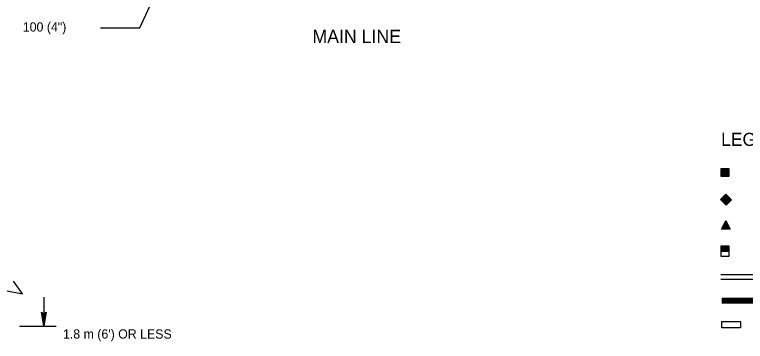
# Model space of a CAD drawing. Extents: x 639362 to 641108, y 298458 to 299646.
# Drawn here: x 639841.8 to 640079.2, y 299345.9 to 299452 of the extents above; entities that cross this region are included whole.
import ezdxf

# ---------------------------------------------------------------- set-up
doc = ezdxf.new("R2010")
doc.units = 0
doc.layers.add('2', color=7, linetype='Continuous')

msp = doc.modelspace()

# ---------------------------------------------------------------- linework, layer by layer
at = {"layer": '2'}
for p, q in [((639882.43, 299447.68), (639888.96, 299461.75)), ((639869.74, 299447.68), (639882.43, 299447.68)), ((640071.33, 299402.08), (640073.83, 299402.08)), ((640071.33, 299399.43), (640071.33, 299402.08)), ((640071.51, 299401.95), (640073.64, 299401.95)), ((640071.51, 299399.55), (640071.51, 299401.95)), ((640071.69, 299401.77), (640073.47, 299401.77)), ((640071.69, 299399.73), (640071.69, 299401.77)), ((640071.87, 299401.59), (640073.29, 299401.59)), ((640071.87, 299399.91), (640071.87, 299401.59)), ((640072.05, 299401.41), (640073.11, 299401.41)), ((640072.05, 299400.08), (640072.05, 299401.41)), ((640072.22, 299400.26), (640072.22, 299401.24)), ((640072.22, 299401.24), (640072.93, 299401.24)), ((640072.93, 299401.24), (640072.93, 299400.26)), ((640073.11, 299401.41), (640073.11, 299400.08)), ((640073.29, 299401.59), (640073.29, 299399.91)), ((640073.47, 299401.77), (640073.47, 299399.73)), ((640073.64, 299401.95), (640073.64, 299399.55)), ((640073.83, 299402.08), (640073.83, 299399.43)), ((640073.83, 299399.43), (640071.33, 299399.43)), ((640073.64, 299399.55), (640071.51, 299399.55)), ((640073.47, 299399.73), (640071.69, 299399.73)), ((640073.29, 299399.91), (640071.87, 299399.91)), ((640073.11, 299400.08), (640072.05, 299400.08)), ((640072.93, 299400.26), (640072.22, 299400.26)), ((640072.4, 299401.06), (640072.76, 299401.06)), ((640072.4, 299400.44), (640072.4, 299401.06)), ((640072.76, 299400.44), (640072.4, 299400.44)), ((640072.58, 299400.88), (640072.58, 299400.62)), ((640072.76, 299401.06), (640072.76, 299400.44)), ((640071.05, 299392.01), (640072.81, 299393.78)), ((640072.92, 299390.14), (640071.05, 299392.01)), ((640071.27, 299392.05), (640072.78, 299393.55)), ((640072.96, 299390.36), (640071.27, 299392.05)), ((640071.52, 299392.05), (640072.78, 299393.31)), ((640072.96, 299390.61), (640071.52, 299392.05)), ((640071.77, 299392.05), (640072.78, 299393.05)), ((640072.96, 299390.86), (640071.77, 299392.05)), ((640072.02, 299392.05), (640072.78, 299392.8)), ((640072.96, 299391.11), (640072.02, 299392.05)), ((640072.28, 299392.05), (640072.78, 299392.55)), ((640072.96, 299391.36), (640072.28, 299392.05)), ((640072.53, 299392.05), (640072.78, 299392.3)), ((640072.97, 299391.61), (640072.53, 299392.05)), ((640072.77, 299392.05), (640072.96, 299391.86)), ((640072.78, 299393.55), (640074.47, 299391.86)), ((640072.78, 299393.31), (640074.22, 299391.86)), ((640072.78, 299393.05), (640073.97, 299391.86)), ((640072.78, 299392.8), (640073.72, 299391.86)), ((640072.78, 299392.55), (640073.47, 299391.86)), ((640072.78, 299392.3), (640073.22, 299391.86)), ((640072.81, 299393.78), (640074.69, 299391.9)), ((640074.69, 299391.9), (640072.92, 299390.14)), ((640074.47, 299391.86), (640072.96, 299390.36)), ((640074.22, 299391.86), (640072.96, 299390.61)), ((640073.97, 299391.86), (640072.96, 299390.86)), ((640073.72, 299391.86), (640072.96, 299391.11)), ((640073.47, 299391.86), (640072.96, 299391.36)), ((640073.22, 299391.86), (640072.97, 299391.61)), ((640071.4, 299382.38), (640072.78, 299385.15)), ((640071.56, 299382.48), (640072.79, 299384.93)), ((640071.72, 299382.58), (640072.78, 299384.71)), ((640072.78, 299385.15), (640074.17, 299382.38)), ((640072.78, 299384.71), (640073.85, 299382.58)), ((640072.79, 299384.93), (640074.01, 299382.48)), ((640074.17, 299382.38), (640071.4, 299382.38)), ((640074.01, 299382.48), (640071.56, 299382.48)), ((640073.85, 299382.58), (640071.72, 299382.58)), ((640071.88, 299382.67), (640072.79, 299384.49)), ((640073.69, 299382.68), (640071.88, 299382.67)), ((640072.04, 299382.78), (640072.79, 299384.27)), ((640073.53, 299382.77), (640072.04, 299382.78)), ((640072.2, 299382.87), (640072.78, 299384.05)), ((640073.37, 299382.87), (640072.2, 299382.87)), ((640072.36, 299382.97), (640072.79, 299383.83)), ((640073.21, 299382.97), (640072.36, 299382.97)), ((640072.52, 299383.08), (640072.78, 299383.6)), ((640073.05, 299383.07), (640072.52, 299383.08)), ((640072.67, 299383.17), (640072.78, 299383.38)), ((640072.89, 299383.17), (640072.67, 299383.17)), ((640072.78, 299384.05), (640073.37, 299382.87)), ((640072.78, 299383.6), (640073.05, 299383.07)), ((640072.78, 299383.38), (640072.89, 299383.17)), ((640072.79, 299384.49), (640073.69, 299382.68)), ((640072.79, 299384.27), (640073.53, 299382.77)), ((640072.79, 299383.83), (640073.21, 299382.97)), ((640071.27, 299376.9), (640073.77, 299376.9)), ((640071.27, 299375.21), (640071.27, 299376.9)), ((640073.77, 299375.21), (640071.27, 299375.21)), ((640071.45, 299376.82), (640073.58, 299376.82)), ((640071.45, 299375.29), (640071.45, 299376.82)), ((640073.58, 299375.29), (640071.45, 299375.29)), ((640071.63, 299376.71), (640073.41, 299376.71)), ((640071.63, 299375.4), (640071.63, 299376.71)), ((640073.41, 299375.4), (640071.63, 299375.4)), ((640071.81, 299376.59), (640073.23, 299376.59)), ((640071.81, 299375.51), (640071.81, 299376.59)), ((640073.23, 299375.51), (640071.81, 299375.51)), ((640071.99, 299376.48), (640073.05, 299376.48)), ((640071.99, 299375.63), (640071.99, 299376.48)), ((640073.05, 299375.63), (640071.99, 299375.63)), ((640072.16, 299375.74), (640072.16, 299376.36)), ((640072.16, 299376.36), (640072.87, 299376.36)), ((640072.87, 299375.74), (640072.16, 299375.74)), ((640072.34, 299376.25), (640072.7, 299376.25)), ((640072.34, 299375.85), (640072.34, 299376.25)), ((640072.7, 299375.85), (640072.34, 299375.85)), ((640072.52, 299376.14), (640072.52, 299375.97)), ((640072.7, 299376.25), (640072.7, 299375.85)), ((640072.87, 299376.36), (640072.87, 299375.74)), ((640073.05, 299376.48), (640073.05, 299375.63)), ((640073.23, 299376.59), (640073.23, 299375.51)), ((640073.41, 299376.71), (640073.41, 299375.4)), ((640073.58, 299376.82), (640073.58, 299375.29)), ((640073.77, 299376.9), (640073.77, 299375.21)), ((640099.48, 299367.51), (640071.19, 299367.51)), ((640099.48, 299366.01), (640071.19, 299366.01)), ((639844.38, 299361.36), (639841.43, 299365.49)), ((639838.86, 299362.49), (639844.38, 299361.36)), ((639851.25, 299360.32), (639851.25, 299350.83)), ((640099.78, 299359.89), (640071.49, 299359.89)), ((640099.78, 299359.74), (640071.49, 299359.74)), ((640099.78, 299359.59), (640071.49, 299359.59)), ((640099.78, 299359.44), (640071.49, 299359.44)), ((640099.78, 299359.29), (640071.49, 299359.29)), ((640099.78, 299359.14), (640071.49, 299359.14)), ((640099.78, 299358.99), (640071.49, 299358.99)), ((640099.78, 299358.84), (640071.49, 299358.84)), ((640099.78, 299358.69), (640071.49, 299358.69)), ((640099.78, 299358.54), (640071.49, 299358.54)), ((640099.78, 299358.39), (640071.49, 299358.39)), ((640071.55, 299350.31), (640071.55, 299352.37)), ((640071.55, 299352.37), (640077.57, 299352.37)), ((640077.57, 299352.37), (640077.57, 299350.31)), ((639843.43, 299350.83), (639855.25, 299350.83)), ((640077.57, 299350.31), (640071.55, 299350.31))]:
    msp.add_line(p, q, dxfattribs=at)
msp.add_lwpolyline([(640071.27, 299375.21), (640073.77, 299375.21), (640073.77, 299373.51), (640071.27, 299373.51)], close=True, dxfattribs=at)
msp.add_lwpolyline([(639851.79, 299355.14), (639851.48, 299354.99), (639851.25, 299350.83), (639851.79, 299355.14), (639851.99, 299355.37), (639851.25, 299350.83), (639851.05, 299354.98), (639850.74, 299355.13), (639851.25, 299350.83), (639850.53, 299355.37), (639850.74, 299355.13)], dxfattribs=at)

# ---------------------------------------------------------------- texts
for s, height, p in [('100 (4")', 3, (639844.45, 299446.52)), ('MAIN LINE', 4.3, (639938.54, 299442.81)), ('LEGEND', 4.25, (640071.27, 299409.4)), ("1.8 m (6') OR LESS", 3, (639857.5, 299346.84))]:
    msp.add_text(s, height=height, dxfattribs=at).set_placement(p)

doc.saveas('drawing.dxf')
